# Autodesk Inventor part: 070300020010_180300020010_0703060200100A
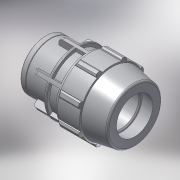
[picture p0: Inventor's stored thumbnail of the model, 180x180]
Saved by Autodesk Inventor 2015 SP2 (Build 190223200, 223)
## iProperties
Created: 2017-02
Part Number: 070300020010_180300020010_0703060200100A
Material: PVC-Piping
Description: PLASSON FEMALE ADAPTOR 20-1"
Document SubType Name: Modeling
Designer: KIM
Mass: 92.6774 g
Surface Area: 199.44 cm^2
Volume: 66.1981 cm^3
Density: 1.4 g/cm^3
Appearance: Smooth - White
Author: KIM
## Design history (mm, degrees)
derived "07030.ipt"
feature "Solid1::07030.ipt"
tag "TaggingFeature1"
body "Solid1"
other parameters: "d4" = 13.14286, "d5" = 23, "d7" = 48, "d9" = 13.14286, "d11" = 2.62857, "d12" = 38.4, "d13" = 120 deg, "d15" = 12 deg, "d16" = 43.2, "d18" = 1, "d19" = 35 deg, "d20" = 17.5 deg, "d21" = 44.64, "d23" = 0, "d25" = 360 deg, "d27" = 0.96, "d34" = 2.4, "d35" = 27.6, "d36" = 0, "d42" = 23, "d43" = 1.44, "d46" = 0.6, "d49" = 57, "d51" = 92, "d53" = 0.4, "d55" = 360 deg, "d61" = 21, "d62" = 16, "d63" = 30.291, "d64" = 30.66667, "d65" = 2.4, "d66" = 0.5, "d67" = 1, "d68" = 6.3, "d69" = 34.56, "d70" = 1.2, "E_" = 48, "H_" = 92, "l_" = 57, "l_2" = 21, "Rp_" = 30.291
